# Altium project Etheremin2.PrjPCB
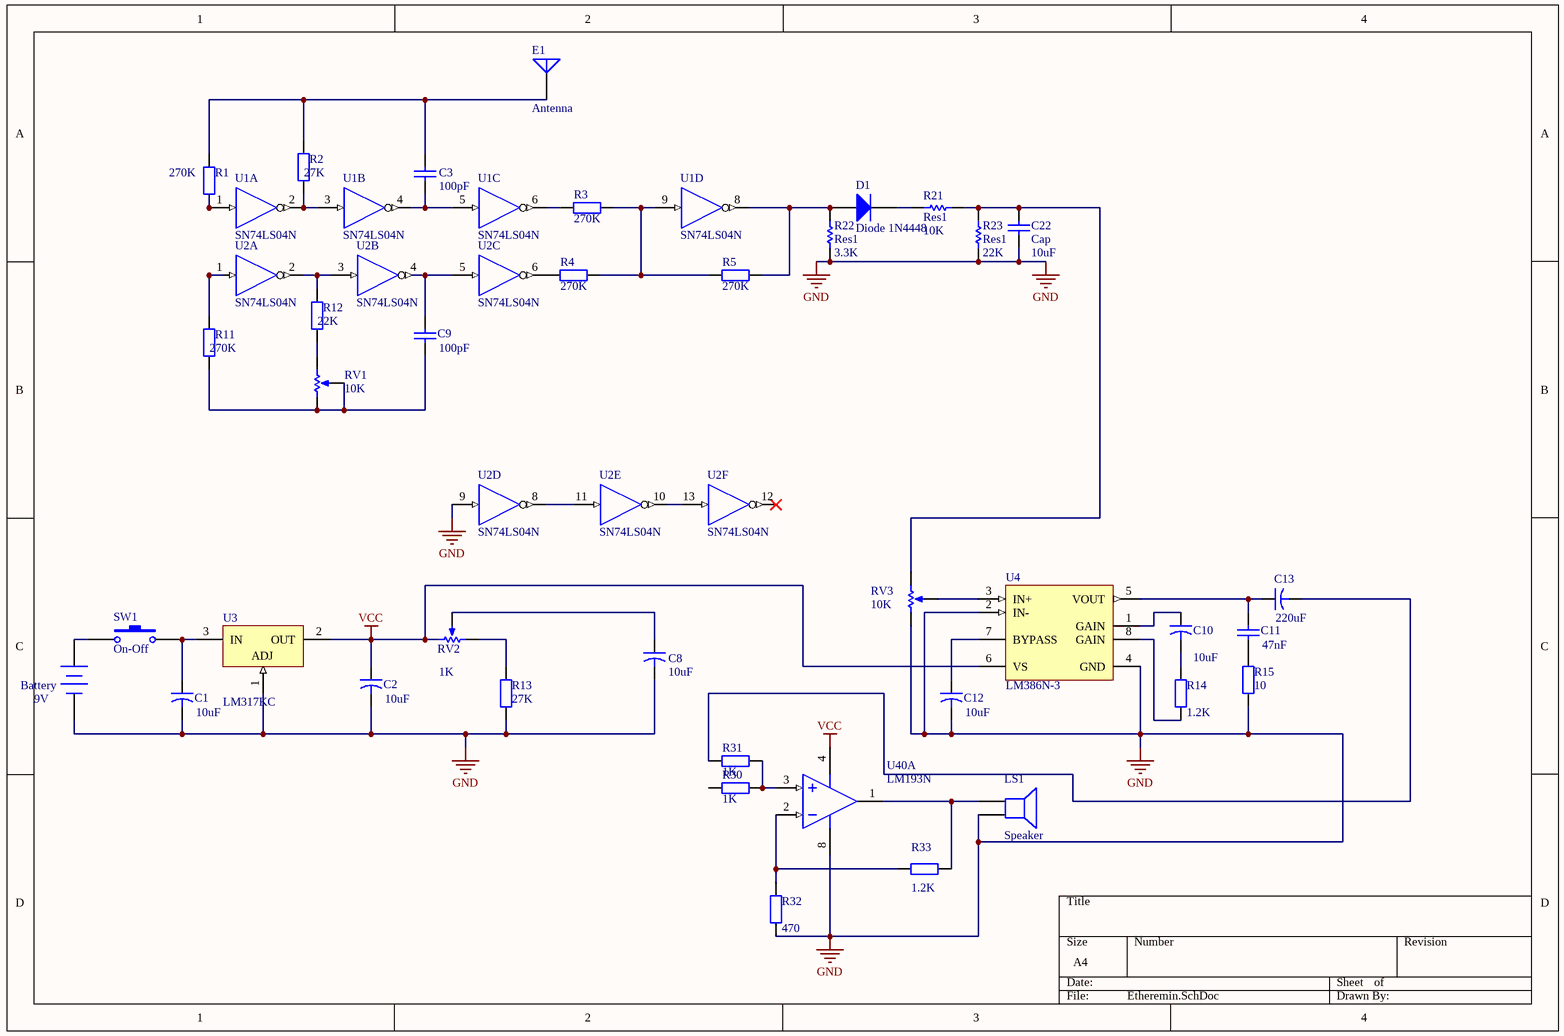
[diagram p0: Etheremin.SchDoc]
1 sheet, 40 parts. Net scope: global (net labels, ports and power ports of the same name join across sheets).
Board file: Etheremin2.PcbDoc

## Sheet Etheremin.SchDoc
size A4

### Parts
9V  Battery  [BAT-2]
C1  value 10uF  [CAPR5-4X5]
C2  value 10uF  [CAPR5-4X5]
C3  value 100pF  [RAD-0.3]
C8  value 10uF  [CAPR5-4X5]
C9  value 100pF  [RAD-0.3]
C10  value 10uF  [CAPR5-4X5]
C11  value 47nF  [RAD-0.3]
C12  value 10uF  [CAPR5-4X5]
C13  value 220uF  [CAPR5-4X5]
C22  Cap  value 10uF  [RAD-0.3]
D1  Diode 1N4448  [DO-35]
E1  Antenna  [PIN1]
LS1  Speaker  [PIN2]
R1  value 270K  [AXIAL-0.4]
R2  value 27K  [AXIAL-0.4]
R3  value 270K  [AXIAL-0.4]
R4  value 270K  [AXIAL-0.4]
R5  value 270K  [AXIAL-0.4]
R11  value 270K  [AXIAL-0.4]
R12  value 22K  [AXIAL-0.4]
R13  value 27K  [AXIAL-0.4]
R14  value 1.2K  [AXIAL-0.4]
R15  value 10  [AXIAL-0.4]
R21  Res1  value 10K  [AXIAL-0.3]
R22  Res1  value 3.3K  [AXIAL-0.3]
R23  Res1  value 22K  [AXIAL-0.3]
R30  value 1K  [AXIAL-0.4]
R31  value 1K  [AXIAL-0.4]
R32  value 470  [AXIAL-0.4]
R33  value 1.2K  [AXIAL-0.4]
RV1  value 10K  [VR5]
RV2  value 1K  [VR5]
RV3  value 10K  [VR5]
SW1  On-Off  [SPST-2]
U1  SN74LS04N  [N014]  (parts A,B,C,D of 6)
U2  SN74LS04N  [N014]  (parts A,B,C,D,E,F of 6)
U3  LM317KC  [KC03]
U4  LM386N-3  [N08E]
U40  LM193N  [DIP8]  (part A of 2)

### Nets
GND: 9V.2(-) C1.2 C2.2 C8.2 C12.2 C22.1 LS1.2 R13.2 R15.2 R22.1 R23.1 R32.1 RV3.1(TOP) U1.7(GND) U2.7(GND) U2.9(A) U3.1(ADJ) U4.2(IN-) U4.4(GND) U40.8(V+)
VCC: C2.1 RV2.2(BOT) U1.14(VCC) U2.14(VCC) U3.2(OUT) U4.6(VS) U40.4(V-)
Net9V_1: 9V.1(+) SW1.1
NetC1_1: C1.1 SW1.2 U3.3(IN)
NetC3_1: C3.1 U1.4(Y) U1.5(A)
NetC3_2: C3.2 E1.1(A) R1.2 R2.2
NetC8_1: C8.1 RV2.3(TAP)
NetC9_1: C9.1 R11.1 RV1.1(TOP) RV1.3(TAP)
NetC9_2: C9.2 U2.4(Y) U2.5(A)
NetC10_1: C10.1 U4.1(GAIN)
NetC10_2: C10.2 R14.1
NetC11_1: C11.1 R15.1
NetC11_2: C11.2 C13.1 U4.5(VOUT)
NetC12_1: C12.1 U4.7(BYPASS)
NetC13_2: C13.2 R31.2
NetC22_2: C22.2 R21.2 R23.2 RV3.2(BOT)
NetD1_1: D1.1(A) R5.1 R22.2 U1.8(Y)
NetD1_2: D1.2(K) R21.1
NetLS1_1: LS1.1 R33.1 U40.1(OUT)
NetR1_1: R1.1 U1.1(A)
NetR2_1: R2.1 U1.2(Y) U1.3(A)
NetR3_1: R3.1 R4.1 R5.2 U1.9(A)
NetR3_2: R3.2 U1.6(Y)
NetR4_2: R4.2 U2.6(Y)
NetR11_2: R11.2 U2.1(A)
NetR12_1: R12.1 RV1.2(BOT)
NetR12_2: R12.2 U2.2(Y) U2.3(A)
NetR13_1: R13.1 RV2.1(TOP)
NetR14_2: R14.2 U4.8(GAIN)
NetR30_1: R30.1 R31.1 U40.3(IN+)
NetR32_2: R32.2 R33.2 U40.2(IN-)
NetRV3_3: RV3.3(TAP) U4.3(IN+)
NetU2_8: U2.8(Y) U2.11(A)
NetU2_10: U2.10(Y) U2.13(A)

Not connected (* = marked no-connect by the designer): R30 2; U2 12(Y)*

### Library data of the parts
9V = Battery: Multicell Battery
C1 C2 C8 C10 C12 C13 = Cap2: Capacitor
C3 C9 C11 C22 = Cap: Capacitor
D1 = Diode 1N4448: High Conductance Fast Diode
E1 = Antenna: Generic Antenna
LS1 = Speaker: Loudspeaker
R1-R5 R11-R15 R30-R33 = Res2: Resistor
R21-R23 = Res1: Resistor
RV1-RV3 = RPot: Potentiometer; Sim Note: Enter the Resistance value and the set point into parameter fields.; Set Position: 0.5
SW1 = SW-PB: Switch
U1 U2 = SN74LS04N: Hex Inverter
U3 = LM317KC: 3-Terminal Adjustable Regulator; Note: Pin 2 is electrically connected to tab
U4 = LM386N-3: Low Voltage Audio Power Amplifier; Manufacturer: National Semiconductor; CompType: Audio IC; PackageTopMarking: NSUZXYTT*LM*386N-3; PowerWise: N
U40 = LM193N: Low-Power Dual Voltage Comparator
